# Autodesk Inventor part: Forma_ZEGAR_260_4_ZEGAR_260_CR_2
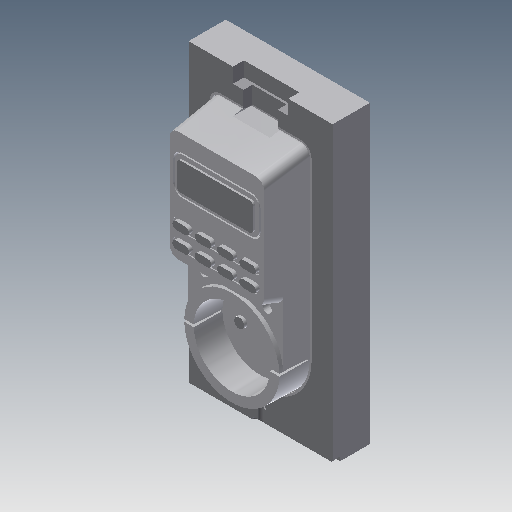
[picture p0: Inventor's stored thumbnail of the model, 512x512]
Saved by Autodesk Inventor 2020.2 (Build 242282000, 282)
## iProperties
Created: 2015-01
Part Number: Forma_ZEGAR_260_4_ZEGAR_260_CR_2
Material: Ogólny
Document SubType Name: Modeling
Designer: F.Stasiak
Density: 1 g/cm^3
Appearance: Domyślna
Catalog Web Link: www.expertbooks.pl
Manager: www.cadconsulting.pl
Company: Fabian Stasiak CAD Consulting
Author: F.Stasiak
Subject: Zbiór ćwiczeń. Autodesk Inventor 2020. Kurs Professional
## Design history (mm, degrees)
node "Forma_ZEGAR_260_4_ZEGAR_260_CR_Base"
feature "Rzeźbienie3"
feature "Bryła1::Forma_ZEGAR_260_4_ZEGAR_260_CR_Base"
tag "Bryła wyprowadzona1"
node "Bryła1"
feature "Forma_ZEGAR_260_4_ZEGAR_260_CR_Base_Bodies"
feature "Powierzchnia3"
body "Srf3"
